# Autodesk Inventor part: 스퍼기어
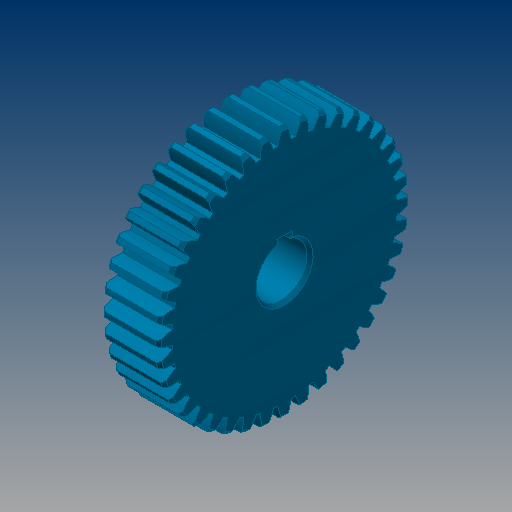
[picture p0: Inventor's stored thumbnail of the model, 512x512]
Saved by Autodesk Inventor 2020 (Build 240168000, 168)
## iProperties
CustomPartVersion: 1
Created: 2018-11
Part Number: 스퍼기어
Material: 알루미늄 6061
Document SubType Name: Modeling
Designer: mduedu
Categories: <?xml version="1.0" encoding="UTF-16"?> <MemberInstance><Categories><FamilyTemplate><FamilyTemplateParameter ValueType="xs:double" Id="1" ObjectReferenceKey="da
Density: 1 g/cm^3
Appearance: 하늘색 중간
Author: mduedu
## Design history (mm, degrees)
sketch "Sketch1"
  geometry: C1 r 42 at (0, 0)
  constraints: 1 centre point
  dimensions: "d0" = 83.99905 diameter of C1 (= da_da)
extrude "Extrusion1" new body sketch "Sketch1" distance "d1" = 19 (= da_b); taper "d2" = 0 deg
workplane "Work Plane2"
sketch "Sketch2"
  geometry: C1 r 42 at (0, 0) reference; C2 r 40.05 at (0, 0)
  constraints: 1 centre point, 1 coincident
  dimensions: "d3" = 80.10038 diameter of C2 (= da_dw)
feature "피치 지름" sketch "Sketch2" dims "d4" = 10, "d5" = 0
workplane "Work Plane8"
workplane "Work Plane9"
feature "스퍼 기어" dims "da_b" = 19, "da_d" = 80, "da_aw" = 80.10038, "da_da" = 83.99905, "da_df" = 75, "da_dw" = 80.10038, angle "da_beta" = 0 deg, "da_lefttooth" = 0, "da_righttooth" = 0
sketch "스케치3"
  geometry: L1 (-42, 19)-(42, 19) reference; L2 (42, 19)-(42, 0) reference; L3 (42, 0)-(-42, 0) reference; L4 (-42, 0)-(-42, 19) reference; L5 (0, 0)-(0, 19); L6 (42, 0)-(41, 0); L7 (42, 1)-(42, 0); L8 (42, 19)-(41, 19); L9 (42, 18)-(42, 19); L10 (41, 19)-(42, 18); L11 (41, 0)-(42, 1)
  constraints: 14 end point, 2 horizontal, 2 vertical, 1 midpoint
  dimensions: "d49" = 1 distance from line of L8.end L2; "d50" = 1 horizontal distance of L8.end L9.start; "d51" = 1 horizontal distance of L6.end L7.start; "d52" = 1 horizontal distance of L6.end L7.start
revolve "회전1" sketch "스케치3" stored, may be unused: angle "d53" = 90 deg
sketch "스케치4"
  geometry: L1 (-2.5, 8.124)-(2.5, 8.124); L2 (2.5, 8.124)-(2.5, 10.8); L3 (2.5, 10.8)-(-2.5, 10.8); L4 (-2.5, 10.8)-(-2.5, 8.124); A1 r 8.5 centre (0, 0) between (-2.5, 8.124) and (2.5, 8.124); 1 further point
  constraints: 8 end point, 2 parallel, 2 point on circle, 1 centre point, 1 coincident, 1 horizontal, 1 perpendicular
  dimensions: "d54" = 17 diameter of A1; "d56" = 19.3 dimension on A1 L3; "d57" = 5 distance of L2.end L3.end
extrude "돌출2" cut sketch "스케치4" extent not by distance; stored distance "d58" = 10; taper "d59" = 0 deg
chamfer "모따기1" distance "d60" = 1; stored, may be unused: second distance "d61" = 2, angle "d62" = 45 deg
sketch "스케치5"
  geometry: C1 r 17.5 at (0, 0); C2 r 28.5 at (0, 0); 1 further point
  constraints: 2 centre point, 2 coincident
  dimensions: "d63" = 35 diameter of C1; "d64" = 57 diameter of C2
extrude "돌출3" cut sketch "스케치5" distance "d65" = 9.5; taper "d66" = 0 deg
fillet "모깎기1" dims "d67" = 3
body "Solid1"
body "Srf1"
node "절단 모서리 투영1"
other parameters: "d16" = 80.10038 (= da_aw), "d17" = 0, "d34" = 4.5 deg (computed from da_z), "d39" = 0, "d41" = 0, "d43" = 80.10038 (= da_aw), "d46" = 80.10038 (= da_aw), "d47" = 0, "d48" = 0
